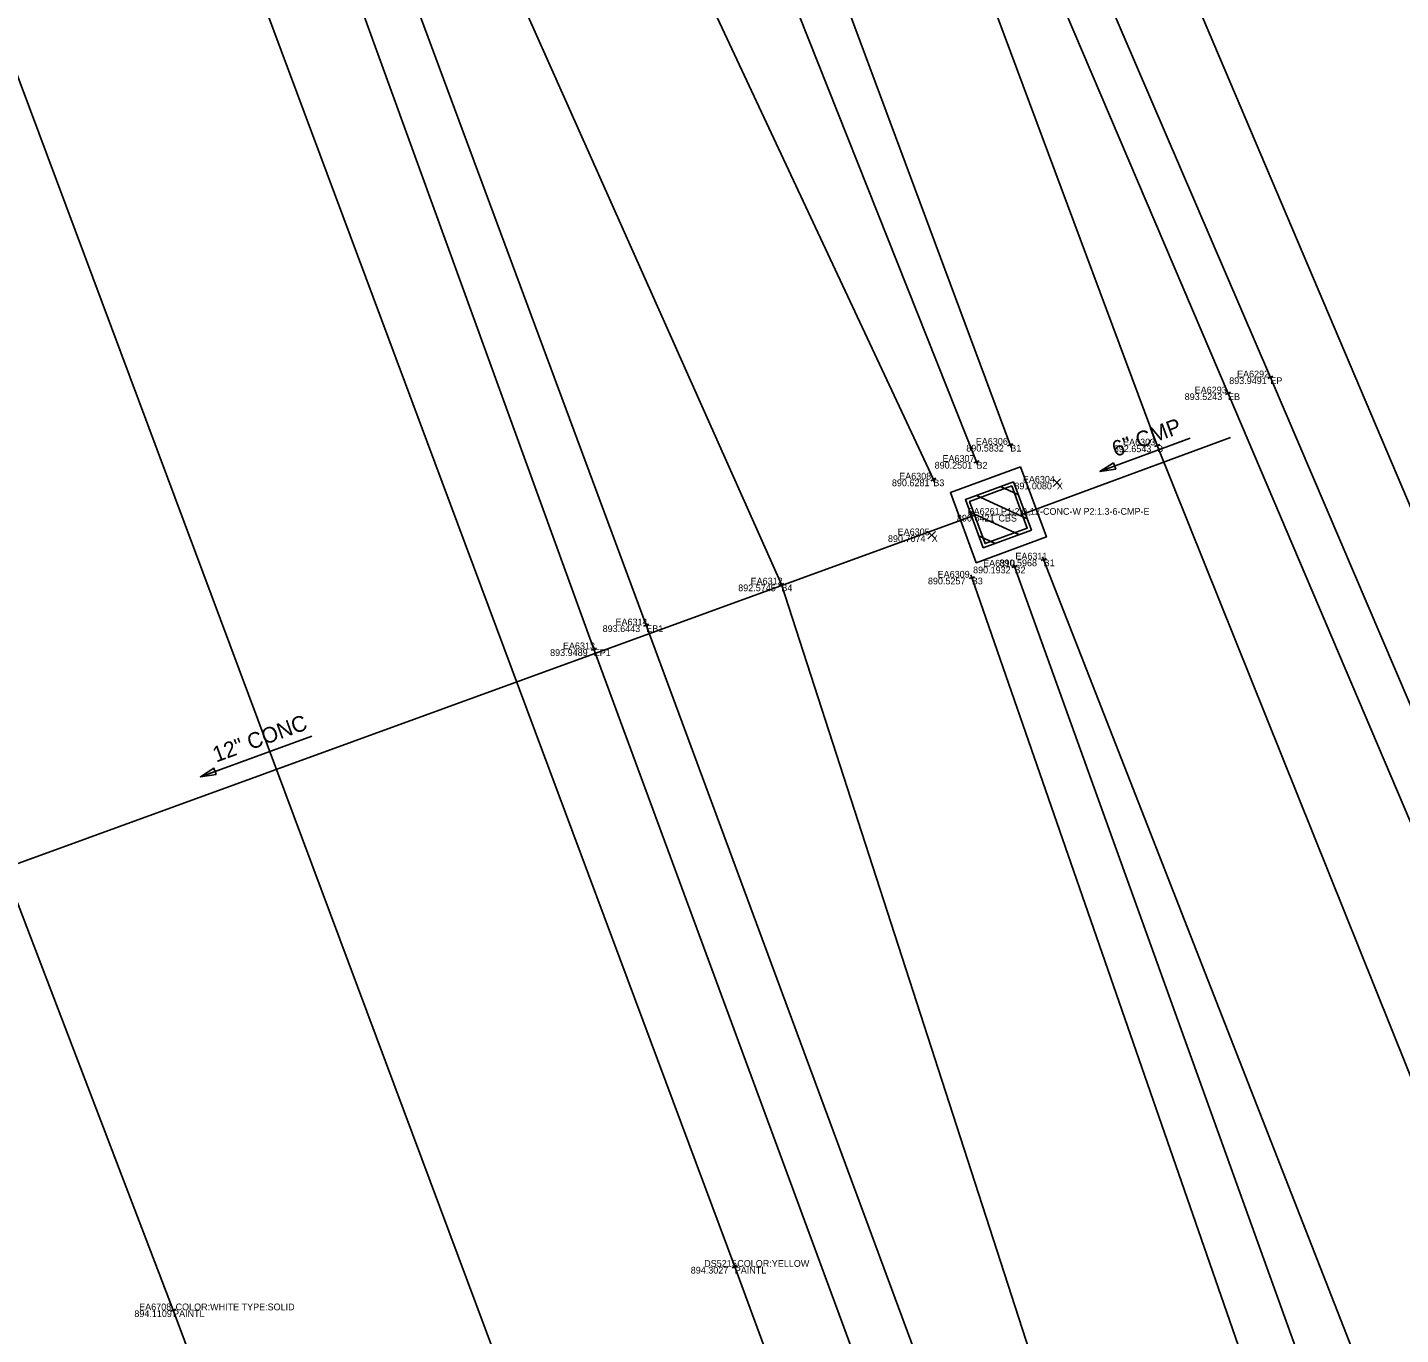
# Model space of a CAD drawing. Extents: x 179049 to 189691, y 286531 to 301260.
# Drawn here: x 180258.4 to 180319.6, y 300466.8 to 300525.1 of the extents above; entities that cross this region are included whole.
import ezdxf

# ---------------------------------------------------------------- set-up
doc = ezdxf.new("R2010")
doc.units = 0
for name, color, linetype in [('Default', 7, 'Continuous'), ('DR_X_Cells', 7, 'Continuous'), ('DR_X_Storm_Sewer', 7, 'Continuous'), ('DR_X_Text', 7, 'Continuous'), ('GK_Drainage_Nodes', 7, 'Continuous'), ('PM_X_Channelizing_Line', 7, 'Continuous'), ('PV_X_COP', 7, 'Continuous'), ('PV_X_EOP', 7, 'Continuous'), ('PV_X_Shoulder_Aggregate', 7, 'Continuous'), ('SV_X_Break_Lines', 7, 'Continuous'), ('SV_X_Random_Point', 7, 'Continuous'), ('SV_X_Shot_Marker', 7, 'Continuous'), ('SV_X_Text_Comment', 7, 'Continuous'), ('SV_X_Text_Description', 7, 'Continuous'), ('SV_X_Text_Elevation', 7, 'Continuous'), ('SV_X_Text_Name', 7, 'Continuous')]:
    doc.layers.add(name, color=color, linetype=linetype)

msp = doc.modelspace()

# ---------------------------------------------------------------- linework, layer by layer
at = {"layer": 'Default'}
for points in [[(180269.952, 300577.657), (180266.311, 300570.1), (180263.372, 300560.932), (180262.77, 300549.441), (180266.986, 300531.433), (180289.954, 300469.854), (180324.352, 300376.444), (180360.496, 300279.469), (180373.081, 300245.703)], [(180416.572, 300274.568), (180407.378, 300298.488), (180397.255, 300322.68), (180377.671, 300368.278), (180338.823, 300459.544), (180302.212, 300545.776), (180296.008, 300558.581), (180288.956, 300567.583), (180278.848, 300574.029), (180270.227, 300577.552)]]:
    msp.add_lwpolyline(points, dxfattribs=at)
at = {"layer": 'DR_X_Cells'}
for p, q in [((180301.794, 300504.62), (180302.6, 300504.248)), ((180301.794, 300504.62), (180302.6, 300504.248)), ((180300.732, 300504.228), (180302.991, 300503.187)), ((180300.732, 300504.228), (180302.991, 300503.187)), ((180300.44, 300503.482), (180302.614, 300502.48)), ((180300.44, 300503.482), (180302.614, 300502.48)), ((180300.831, 300502.421), (180301.552, 300502.088)), ((180300.831, 300502.421), (180301.552, 300502.088))]:
    msp.add_line(p, q, dxfattribs=at)
for points in [[(180302.691, 300505.506), (180303.844, 300502.378), (180300.717, 300501.225), (180299.564, 300504.352)], [(180302.691, 300505.506), (180303.844, 300502.378), (180300.717, 300501.225), (180299.564, 300504.352)], [(180302.383, 300504.837), (180303.175, 300502.687), (180301.025, 300501.894), (180300.232, 300504.044)], [(180302.383, 300504.837), (180303.175, 300502.687), (180301.025, 300501.894), (180300.232, 300504.044)], [(180302.296, 300504.65), (180302.988, 300502.773), (180301.112, 300502.081), (180300.42, 300503.958)], [(180302.296, 300504.65), (180302.988, 300502.773), (180301.112, 300502.081), (180300.42, 300503.958)]]:
    msp.add_lwpolyline(points, close=True, dxfattribs=at)
at = {"layer": 'DR_X_Storm_Sewer'}
for p, q in [((180302.704, 300503.365), (180312.049, 300506.806)), ((180300.704, 300503.365), (180226.568, 300476.391))]:
    msp.add_line(p, q, dxfattribs=at)
at = {"layer": 'DR_X_Text'}
for p, q in [((180310.249, 300506.782), (180306.226, 300505.301)), ((180271.105, 300493.5), (180266.14, 300491.694))]:
    msp.add_line(p, q, dxfattribs=at)
for points in [[(180306.831, 300505.684), (180306.935, 300505.403), (180306.226, 300505.301)], [(180266.849, 300491.792), (180266.746, 300492.074), (180266.14, 300491.694)]]:
    msp.add_lwpolyline(points, close=True, dxfattribs=at)
at = {"layer": 'GK_Drainage_Nodes'}
for p, q in [((180301.358, 300504.304), (180301.358, 300504.304)), ((180301.358, 300504.304), (180301.358, 300504.304)), ((180303.268, 300503.942), (180303.268, 300503.942)), ((180303.268, 300503.942), (180303.268, 300503.942)), ((180301.704, 300503.365), (180301.704, 300503.365)), ((180301.704, 300503.365), (180301.704, 300503.365)), ((180301.704, 300503.365), (180301.704, 300503.365)), ((180301.704, 300503.365), (180301.704, 300503.365)), ((180301.704, 300503.365), (180301.704, 300503.365)), ((180301.704, 300503.365), (180301.704, 300503.365)), ((180302.642, 300503.711), (180302.642, 300503.711)), ((180302.642, 300503.711), (180302.642, 300503.711)), ((180300.14, 300502.789), (180300.14, 300502.789)), ((180300.14, 300502.789), (180300.14, 300502.789)), ((180300.766, 300503.019), (180300.766, 300503.019)), ((180300.766, 300503.019), (180300.766, 300503.019)), ((180302.05, 300502.427), (180302.05, 300502.427)), ((180302.05, 300502.427), (180302.05, 300502.427))]:
    msp.add_line(p, q, dxfattribs=at)
at = {"layer": 'PM_X_Channelizing_Line'}
msp.add_lwpolyline([(180190.445, 300582.496), (180201.741, 300580.903), (180210.797, 300577.931), (180219.101, 300571.651), (180228.235, 300559.496), (180237.94, 300538.543), (180264.924, 300467.918), (180293.4, 300391.707), (180324.643, 300308.043), (180350.475, 300238.896)], dxfattribs=at)
at = {"layer": 'PV_X_COP'}
msp.add_lwpolyline([(180246.716, 300553.114), (180279.248, 300465.999), (180313.722, 300372.324), (180349.437, 300276.58), (180362.146, 300242.511)], dxfattribs=at)
at = {"layer": 'PV_X_EOP'}
for points in [[(180275.541, 300570.539), (180270.388, 300566.454), (180267.273, 300561.588), (180266.459, 300554.084), (180265.761, 300546.765), (180283.67, 300497.374), (180310.435, 300424.792), (180336.457, 300355.213), (180379.468, 300239.43)], [(180275.541, 300570.539), (180281.08, 300569.395), (180286.302, 300565.407), (180291.485, 300559.019), (180299.83, 300542.045), (180313.822, 300509.489), (180346.033, 300434.084), (180370.964, 300374.351), (180403.471, 300297.797), (180418.39, 300258.269)]]:
    msp.add_lwpolyline(points, dxfattribs=at)
at = {"layer": 'PV_X_Shoulder_Aggregate'}
for points in [[(180276.015, 300565.593), (180281.288, 300566.161), (180286.068, 300563.144), (180298.579, 300540.14), (180311.937, 300508.777), (180343.813, 300433.852), (180369.171, 300373.38), (180401.131, 300296.715), (180416.281, 300257.534)], [(180276.015, 300565.593), (180272.424, 300562.362), (180270.301, 300554.787), (180269.122, 300543.981), (180286.011, 300498.44), (180312.867, 300425.83), (180338.723, 300356.477), (180381.308, 300240.575)]]:
    msp.add_lwpolyline(points, dxfattribs=at)
at = {"layer": 'SV_X_Break_Lines'}
for points in [[(180285.869, 300558.023), (180297.684, 300536.245), (180308.778, 300506.456), (180338.649, 300432.1), (180367.2, 300369.993), (180410.141, 300254.681)], [(180281.085, 300555.439), (180289.69, 300533.513), (180300.73, 300505.723)], [(180284.601, 300552.482), (180292.195, 300533.463), (180302.232, 300506.484)], [(180278.676, 300551.659), (180285.337, 300533.721), (180298.804, 300504.938)], [(180274.364, 300549.595), (180277.806, 300532.178), (180292.031, 300500.259), (180315.947, 300426.336), (180343.875, 300357.803), (180387.064, 300242.808)], [(180302.421, 300501.058), (180327.985, 300430.042), (180355.523, 300363.079), (180398.147, 300248.566)], [(180303.72, 300501.373), (180331.456, 300430.396), (180357.818, 300364.306), (180401.637, 300249.805)], [(180300.517, 300500.565), (180325.39, 300428.896), (180352.275, 300361.992), (180395.375, 300246.26)]]:
    msp.add_lwpolyline(points, dxfattribs=at)
at = {"layer": 'SV_X_Random_Point'}
for p, q in [((180304.144, 300504.632), (180304.477, 300504.965)), ((180304.144, 300504.965), (180304.477, 300504.632)), ((180298.565, 300502.287), (180298.898, 300502.621)), ((180298.565, 300502.621), (180298.898, 300502.287))]:
    msp.add_line(p, q, dxfattribs=at)
at = {"layer": 'SV_X_Shot_Marker'}
for p, q in [((180313.937, 300509.538), (180313.708, 300509.44)), ((180313.773, 300509.604), (180313.872, 300509.374)), ((180313.822, 300509.489), (180313.822, 300509.489)), ((180312.052, 300508.826), (180311.822, 300508.728)), ((180311.888, 300508.892), (180311.986, 300508.662)), ((180311.937, 300508.777), (180311.937, 300508.777)), ((180302.35, 300506.527), (180302.115, 300506.44)), ((180302.189, 300506.601), (180302.276, 300506.367)), ((180302.232, 300506.484), (180302.232, 300506.484)), ((180308.895, 300506.5), (180308.661, 300506.412)), ((180308.735, 300506.573), (180308.822, 300506.339)), ((180308.778, 300506.456), (180308.778, 300506.456)), ((180300.846, 300505.769), (180300.614, 300505.677)), ((180300.684, 300505.839), (180300.776, 300505.607)), ((180300.73, 300505.723), (180300.73, 300505.723)), ((180298.917, 300504.991), (180298.69, 300504.885)), ((180298.751, 300505.052), (180298.857, 300504.825)), ((180298.804, 300504.938), (180298.804, 300504.938)), ((180303.836, 300501.419), (180303.603, 300501.328)), ((180303.674, 300501.49), (180303.765, 300501.257)), ((180302.538, 300501.101), (180302.303, 300501.016)), ((180302.378, 300501.176), (180302.463, 300500.941)), ((180302.421, 300501.058), (180302.421, 300501.058)), ((180303.72, 300501.373), (180303.72, 300501.373)), ((180292.146, 300500.31), (180291.917, 300500.208)), ((180291.981, 300500.373), (180292.082, 300500.145)), ((180292.031, 300500.259), (180292.031, 300500.259)), ((180300.635, 300500.606), (180300.399, 300500.524)), ((180300.476, 300500.683), (180300.558, 300500.447)), ((180300.517, 300500.565), (180300.517, 300500.565)), ((180286.128, 300498.484), (180285.893, 300498.397)), ((180285.967, 300498.558), (180286.054, 300498.323)), ((180286.011, 300498.44), (180286.011, 300498.44)), ((180283.788, 300497.416), (180283.552, 300497.331)), ((180283.627, 300497.491), (180283.713, 300497.256)), ((180283.67, 300497.374), (180283.67, 300497.374)), ((180290.071, 300469.897), (180289.837, 300469.81)), ((180289.91, 300469.971), (180289.997, 300469.736)), ((180289.954, 300469.854), (180289.954, 300469.854)), ((180265.041, 300467.963), (180264.807, 300467.874)), ((180264.88, 300468.035), (180264.969, 300467.801)), ((180264.924, 300467.918), (180264.924, 300467.918))]:
    msp.add_line(p, q, dxfattribs=at)

# ---------------------------------------------------------------- texts
at = {"layer": 'DR_X_Text'}
for s, rotation, p in [('6" CMP', 20.21069, (180306.926, 300505.932)), ('12" CONC', 19.99419, (180266.842, 300492.322))]:
    msp.add_text(s, height=0.7, rotation=rotation, dxfattribs=at).set_placement(p)
at = {"layer": 'SV_X_Text_Comment'}
for s, height, p in [('EP', 0.3, (180313.822, 300509.189)), ('EB', 0.3, (180311.937, 300508.477)), ('B1', 0.3, (180302.232, 300506.184)), ('B', 0.3, (180308.778, 300506.156)), ('B2', 0.3, (180300.73, 300505.423)), ('B3', 0.3, (180298.804, 300504.638)), ('X', 0.3, (180304.31, 300504.498)), ('P1=2.0-12-CONC-W P2=1.3-6-CMP-E', 0.06, (180301.704, 300503.305)), ('CBS', 0.3, (180301.704, 300503.065)), ('X', 0.3, (180298.732, 300502.154)), ('B2', 0.3, (180302.421, 300500.758)), ('B1', 0.3, (180303.72, 300501.073)), ('B4', 0.3, (180292.031, 300499.959)), ('B3', 0.3, (180300.517, 300500.265)), ('EB1', 0.3, (180286.011, 300498.14)), ('EP1', 0.3, (180283.67, 300497.074)), ('PAINTL', 0.3, (180289.954, 300469.554)), ('PAINTL', 0.3, (180264.924, 300467.618))]:
    msp.add_text(s, height=height, dxfattribs=at).set_placement(p)
at = {"layer": 'SV_X_Text_Description'}
for s, height, p in [('P1= 2.0-12-CONC-W  P2=1.3-6-CMP-E', 0.06, (180301.704, 300503.365)), (' P1:2.0-12-CONC-W P2:1.3-6-CMP-E', 0.3, (180301.704, 300503.365)), (' COLOR:YELLOW', 0.3, (180289.954, 300469.854)), (' COLOR:WHITE TYPE:SOLID', 0.3, (180264.924, 300467.918))]:
    msp.add_text(s, height=height, dxfattribs=at).set_placement(p)
at = {"layer": 'SV_X_Text_Elevation'}
for s, height, p in [('893.9491', 0.3, (180311.989, 300509.189)), ('893.5243', 0.3, (180310.005, 300508.477)), ('890.5832', 0.3, (180300.272, 300506.184)), ('892.6543', 0.3, (180306.846, 300506.156)), ('890.2501', 0.3, (180298.861, 300505.423)), ('890.6281', 0.3, (180296.958, 300504.638)), ('891.0080', 0.3, (180302.416, 300504.498)), ('890.6421', 0.3, (180299.856, 300503.065)), ('890.64', 0.06, (180301.416, 300503.305)), ('890.7674', 0.3, (180296.781, 300502.154)), ('890.1932', 0.3, (180300.574, 300500.758)), ('890.5968', 0.3, (180301.75, 300501.073)), ('892.5745', 0.3, (180290.109, 300499.959)), ('890.5257', 0.3, (180298.563, 300500.265)), ('893.6443', 0.3, (180284.067, 300498.14)), ('893.9489', 0.3, (180281.726, 300497.074)), ('894.3027', 0.3, (180287.993, 300469.554)), ('894.1109', 0.3, (180263.198, 300467.618))]:
    msp.add_text(s, height=height, dxfattribs=at).set_placement(p)
at = {"layer": 'SV_X_Text_Name'}
for s, height, p in [('EA6292', 0.3, (180312.339, 300509.489)), ('EA6293', 0.3, (180310.452, 300508.777)), ('EA6306', 0.3, (180300.695, 300506.484)), ('EA6303', 0.3, (180307.26, 300506.456)), ('EA6307', 0.3, (180299.211, 300505.723)), ('EA6308', 0.3, (180297.282, 300504.938)), ('EA6304', 0.3, (180302.794, 300504.798)), ('EA6261', 0.3, (180300.331, 300503.365)), ('EA6261', 0.06, (180301.429, 300503.365)), ('EA6305', 0.3, (180297.213, 300502.454)), ('EA6311', 0.3, (180302.461, 300501.373)), ('EA6309', 0.3, (180298.996, 300500.565)), ('EA6310', 0.3, (180301.022, 300501.058)), ('EA6312', 0.3, (180290.662, 300500.259)), ('EA6314', 0.3, (180284.641, 300498.44)), ('EA6313', 0.3, (180282.298, 300497.374)), ('DS5215', 0.3, (180288.593, 300469.854)), ('EA6708', 0.3, (180263.413, 300467.918))]:
    msp.add_text(s, height=height, dxfattribs=at).set_placement(p)

doc.saveas('drawing.dxf')
